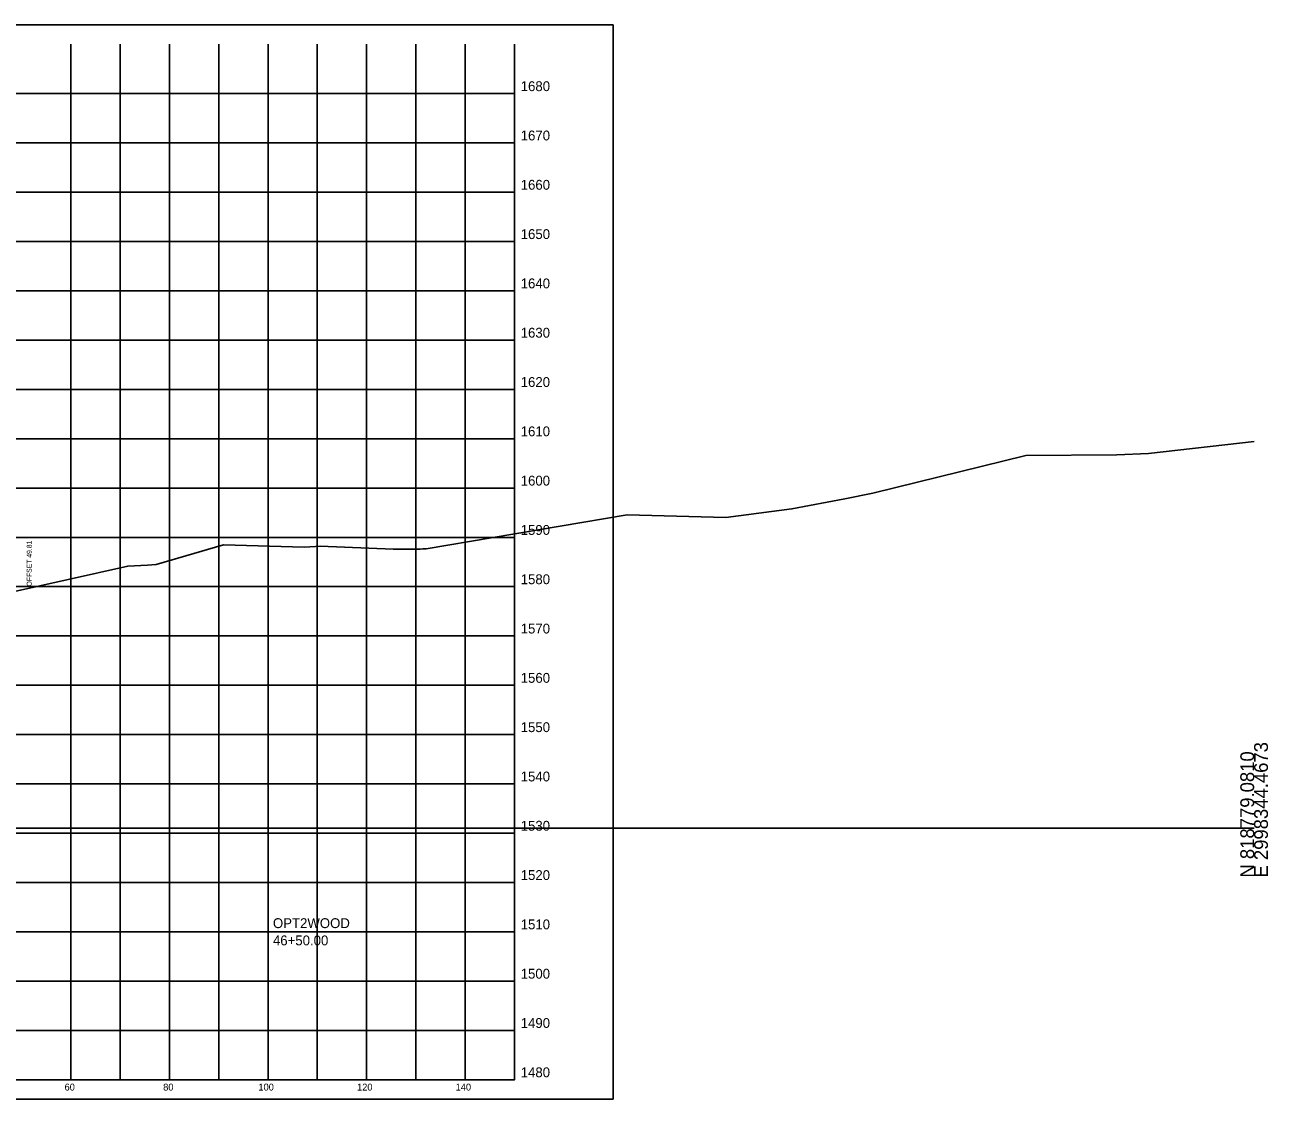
# Model space of a CAD drawing. Extents: x -26 to 2998798, y -429 to 819149.
# Drawn here: x 350.7 to 602.8, y 1945.1 to 2162.9 of the extents above; entities that cross this region are included whole.
import ezdxf

# ---------------------------------------------------------------- set-up
doc = ezdxf.new("R2010")
doc.units = 0
for name, color, linetype in [('DESIGN - SHEET - Corner Text', 7, 'Continuous'), ('DESIGN - SHEET - Light Grid', 7, 'Continuous'), ('DESIGN - SHEET - Linework', 7, 'Continuous'), ('DESIGN - SHEET - Plot Shape', 7, 'Continuous'), ('DESIGN - TYPICAL - Slope Tie Text', 7, 'Continuous'), ('DESIGN - TYPICAL - Warning Text', 7, 'Continuous'), ('SURVEY - GROUND - Top of Ground', 7, 'Continuous')]:
    doc.layers.add(name, color=color, linetype=linetype)

msp = doc.modelspace()

# ---------------------------------------------------------------- linework, layer by layer
at = {"layer": 'DESIGN - SHEET - Light Grid'}
msp.add_line((300, 2000), (600, 2000), dxfattribs=at)
at = {"layer": 'DESIGN - SHEET - Linework'}
for p, q in [((360, 1949), (360, 2159)), ((370, 1949), (370, 2159)), ((380, 1949), (380, 2159)), ((390, 1949), (390, 2159)), ((400, 1949), (400, 2159)), ((410, 1949), (410, 2159)), ((420, 1949), (420, 2159)), ((430, 1949), (430, 2159)), ((440, 1949), (440, 2159)), ((150, 2149), (450, 2149)), ((150, 2139), (450, 2139)), ((150, 2129), (450, 2129)), ((150, 2119), (450, 2119)), ((150, 2109), (450, 2109)), ((150, 2099), (450, 2099)), ((150, 2089), (450, 2089)), ((150, 2079), (450, 2079)), ((150, 2069), (450, 2069)), ((150, 2059), (450, 2059)), ((150, 2049), (450, 2049)), ((150, 2039), (450, 2039)), ((150, 2029), (450, 2029)), ((150, 2019), (450, 2019)), ((150, 2009), (450, 2009)), ((150, 1999), (450, 1999)), ((150, 1989), (450, 1989)), ((150, 1979), (450, 1979)), ((150, 1969), (450, 1969)), ((150, 1959), (450, 1959))]:
    msp.add_line(p, q, dxfattribs=at)
msp.add_lwpolyline([(150, 2159), (150, 1949), (450, 1949), (450, 2159)], dxfattribs=at)
at = {"layer": 'DESIGN - SHEET - Plot Shape'}
msp.add_lwpolyline([(130, 2162.94), (470, 2162.94), (470, 1945.06), (130, 1945.06)], close=True, dxfattribs=at)
at = {"layer": 'SURVEY - GROUND - Top of Ground'}
msp.add_lwpolyline([(347.4, 2047.73), (371.54, 2053.17), (375.58, 2053.39), (377.34, 2053.49), (391, 2057.45), (407.36, 2057.03), (408.49, 2057.09), (409.61, 2057.14), (410.56, 2057.19), (425.35, 2056.6), (429.99, 2056.62), (430.88, 2056.63), (431.38, 2056.7), (432.06, 2056.7), (472.87, 2063.57), (492.82, 2063.04), (506.26, 2064.78), (516.97, 2066.8), (522.68, 2067.97), (553.71, 2075.58), (572.18, 2075.72), (578.56, 2076.01), (600, 2078.46)], dxfattribs=at)

# ---------------------------------------------------------------- texts
at = {"layer": 'DESIGN - SHEET - Corner Text'}
for s, height, p in [('1680', 2, (451.25, 2149.5)), ('1670', 2, (451.25, 2139.5)), ('1660', 2, (451.25, 2129.5)), ('1650', 2, (451.25, 2119.5)), ('1640', 2, (451.25, 2109.5)), ('1630', 2, (451.25, 2099.5)), ('1620', 2, (451.25, 2089.5)), ('1610', 2, (451.25, 2079.5)), ('1600', 2, (451.25, 2069.5)), ('1590', 2, (451.25, 2059.5)), ('1580', 2, (451.25, 2049.5)), ('1570', 2, (451.25, 2039.5)), ('1560', 2, (451.25, 2029.5)), ('1550', 2, (451.25, 2019.5)), ('1540', 2, (451.25, 2009.5)), ('1530', 2, (451.25, 1999.5)), ('1520', 2, (451.25, 1989.5)), ('1510', 2, (451.25, 1979.5)), ('1500', 2, (451.25, 1969.5)), ('1490', 2, (451.25, 1959.5)), ('1480', 2, (451.25, 1949.5)), ('60', 1.4, (358.74, 1946.8)), ('80', 1.4, (378.74, 1946.8)), ('100', 1.4, (398.06, 1946.8)), ('120', 1.4, (418.06, 1946.8)), ('140', 1.4, (438.06, 1946.8))]:
    msp.add_text(s, height=height, dxfattribs=at).set_placement(p)
at = {"layer": 'DESIGN - SHEET - Light Grid'}
for s, p in [('E 2998344.4673', (602.8, 1990)), ('N 818779.0810', (600, 1990))]:
    msp.add_text(s, height=2.8, rotation=90, dxfattribs=at).set_placement(p)
at = {"layer": 'DESIGN - TYPICAL - Slope Tie Text'}
msp.add_text('OFFSET 49.81', height=1, rotation=90, dxfattribs=at).set_placement((352.06, 2049.04))
at = {"layer": 'DESIGN - TYPICAL - Warning Text'}
for s, p in [('OPT2WOOD', (401, 1979.75)), ('46+50.00', (401, 1976.25))]:
    msp.add_text(s, height=2, dxfattribs=at).set_placement(p)

doc.saveas('drawing.dxf')
